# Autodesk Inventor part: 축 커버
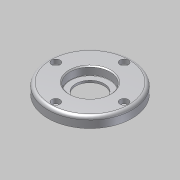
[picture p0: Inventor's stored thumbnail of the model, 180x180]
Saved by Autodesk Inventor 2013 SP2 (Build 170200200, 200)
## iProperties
Created: 2013-06
Part Number: 축 커버
Document SubType Name: Modeling
Designer: SeoGD™[esajin.kr]
Density: 1 g/cm^3
Material: 일반
Mass: 41.026 g
Surface Area: 133.703 cm^2
Volume: 41.026 cm^3
Author: SeoGD™[esajin.kr]
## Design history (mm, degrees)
sketch "스케치1"
  geometry: C1 r 40 at (0, 0) reference; C2 r 26 at (0, 0) reference; 1 further point
  node "참조1"
  node "참조2"
extrude "돌출1" new body sketch "스케치1" distance "d0" = 10; taper "d1" = 0 deg
extrude "돌출2" join sketch "스케치1" distance "d2" = 3; taper "d3" = 0 deg
hole "구멍1" diameter "d6" = 27; stored, may be unused: countersink angle "d10" = 90 deg, drill point angle "d12" = 118 deg; dims "d4" = 10, "d5" = 10, "d7" = 6, "d8" = 38, "d9" = 8, "d11" = 8
sketch "스케치2"
  geometry: C1 r 20 at (0, 0); 1 further point
  constraints: 1 centre point, 1 coincident
  dimensions: "d13" = 40 diameter of C1
extrude "돌출3" cut sketch "스케치2" distance "d14" = 3; taper "d15" = 0 deg
sketch "스케치3"
  geometry: C1 r 1.621 at (0, 32.5) reference; 1 further point
hole "구멍2" sketch "스케치3" at (0, 32.5) diameter "d16" = 4.5; stored, may be unused: countersink angle "d20" = 90 deg, drill point angle "d22" = 118 deg; dims "d17" = 6, "d18" = 8, "d19" = 4.4, "d21" = 8
fillet "모깎기1" dims "d26" = 3, "d27" = 0.3
chamfer "모따기1" distance "d28" = 1; stored, may be unused: second distance "d29" = 2, angle "d30" = 45 deg
node "솔리드1"
pattern_circular "원형 패턴1" dims angle "d24" = 360 deg
node "참조3"
